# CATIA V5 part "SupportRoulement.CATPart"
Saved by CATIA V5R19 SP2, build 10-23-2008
Part number: PorteRoulement
Bounding box of the stored display mesh (mm): x 0 to 30, y 0 to 80, z 0 to 100
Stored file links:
  D:\SCHOOL\FRANCE\BANC_POUTRE_EN_MOUSSE\SupportRoulement.CATPart
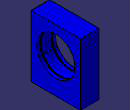
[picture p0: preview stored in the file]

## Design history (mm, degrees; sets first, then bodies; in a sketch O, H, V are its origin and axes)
AxisSystem1: origin (0, 0, 0), X (1, 0, 0), Y (0, 1, 0), Z (0, 0, 1)
Set1
  Sketch1 on YZ plane of AxisSystem1, origin (0, 0, 0), H (0, 1, 0), V (0, 0, 1)
    line L1 (0, 0) -> (80, 0)
    line L2 (80, 0) -> (80, 100)
    line L3 (80, 100) -> (0, 100)
    point P3 (0, 100)
    line L4 (0, 100) -> (0, 0)
    length L4 = 100
    length L1 = 80
    horizontal: L1 H, L3 H
    vertical: L2 V, L4 V
    coincidence: P3 V
  Plane1: type Offset, RefPlane YZ plane of AxisSystem1, Offset 7
  Plane2: type Offset, RefPlane YZ plane of AxisSystem1, Offset 23
Body1 (main body)
  Pad1: profile Sketch1, direction (1, 0, 0), length 30
  Sketch2 on face of Pad1 from Sketch1.L1, origin (11.8537, 19.664, 0), H (1, 0, 0), V (0, -1, 0)
    point P1 (0, -0.336)
    reference intersected line E1 through (0, 19.664) direction (1, 0) from ZX plane of AxisSystem1
    reference intersected line E2 through (-11.8537, 0) direction (0, 1) from YZ plane of AxisSystem1
    distance E1 P1 = 20
    distance E2 V = 12
  Hole1: placed by Sketch2, at (11.8537, 20, 0) direction (0, 0, 1), diameter 4.917, depth 10, threaded "M6", thread diameter 6, thread depth 10, pitch 1
  RectPattern1: of Hole1, direction 1 instances 2, spacing 40, along edge [face of Pad1 from Sketch1.L1 | end face of Pad1]
  Sketch3 on start face of Pad1, origin (0, 42.2334, 56.6197), H (0, 1, 0), V (0, 0, -1)
    point P1 (-2.2334, 0.6197)
    reference projected line E1 (-42.2334, 56.6197) -> (37.7666, 56.6197) from edge [start face of Pad1 | face of Pad1 from Sketch1.L1]
    reference projected line E2 (-42.2334, -23.3803) -> (-42.2334, 56.6197) from edge [start face of Pad1 | face of Pad1 from Sketch1.L4]
    distance E1 P1 = 56
    distance E2 P1 = 40
  Hole2: placed by Sketch3, at (0, 40, 56) direction (1, 0, 0), diameter 62, through (limit type 6)
  Sketch4 on start face of Pad1, origin (0, 59.7058, 17.5814), H (0, 1, 0), V (0, 0, -1)
    point P1 (0.2942, 7.5814)
    reference projected line E1 (-59.7058, 17.5814) -> (20.2942, 17.5814) from edge [start face of Pad1 | face of Pad1 from Sketch1.L1]
    reference projected line E2 (20.2942, 17.5814) -> (20.2942, -62.4186) from edge [start face of Pad1 | face of Pad1 from Sketch1.L2]
    distance E1 P1 = 10
    distance E2 P1 = 20
  Hole3: placed by Sketch4, at (0, 60, 10) direction (1, 0, 0), diameter 4.917, depth 10, threaded "M6", thread diameter 6, thread depth 10, pitch 1
  RectPattern2: of Hole3, direction 1 instances 2, spacing 40, along edge [start face of Pad1 | face of Pad1 from Sketch1.L3]
  Sketch5 on face of Pad1 from Sketch1.L1, origin (10.8976, 38.3868, 0), H (1, 0, 0), V (0, -1, 0)
    point P1 (1.1024, -1.6132)
    reference intersected line E1 through (0, 38.3868) direction (1, 0) from ZX plane of AxisSystem1
    reference intersected line E2 through (-10.8976, 0) direction (0, 1) from YZ plane of AxisSystem1
    distance E1 P1 = 40
    distance E2 P1 = 12
  Hole4: placed by Sketch5, at (12, 40, 0) direction (0, 0, 1), diameter 4.917, depth 10, threaded "M6", thread diameter 6, thread depth 5, pitch 1
  Sketch6 on Plane1, origin (7, 0, 0), H (0, 1, 0), V (0, 0, 1)
    circle A1 centre (40, 56) radius 32.5
    reference projected circle E1 centre (40, 56) radius 31 from edge [end face of Pad1 | face of Hole2]
    radius A1 = 32.5
    concentricity: A1 E1
  Pocket1: profile Sketch6, direction (-1, 0, 0), length 2
  Sketch7 on Plane2, origin (23, 0, 0), H (0, 1, 0), V (0, 0, 1)
    circle A1 centre (40, 56) radius 32.5
    reference projected circle E1 centre (40, 56) radius 31 from edge [end face of Pad1 | face of Hole2]
    radius A1 = 32.5
    concentricity: A1 E1
  Pocket2: profile Sketch7, direction (1, 0, 0), length 2
  Sketch8 on face of Pad1 from Sketch1.L1, origin (0, 0, 0), H (0, 1, 0), V (1, 0, 0)
    line L1 (0, 0) -> (80, 0)
    line L2 (80, 0) -> (80, 100)
    line L3 (80, 100) -> (0, 100)
    point P3 (0, 100)
    line L4 (0, 100) -> (0, 0)
    circle A1 centre (40, 56) radius 21
    point P4 (40, 56)
    length L4 = 100
    length L1 = 80
    radius A1 = 21
    distance L1 P4 = 56
    distance L4 P4 = 40
    horizontal: L1 H, L3 H
    vertical: L2 V, L4 V
    coincidence: P3 V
